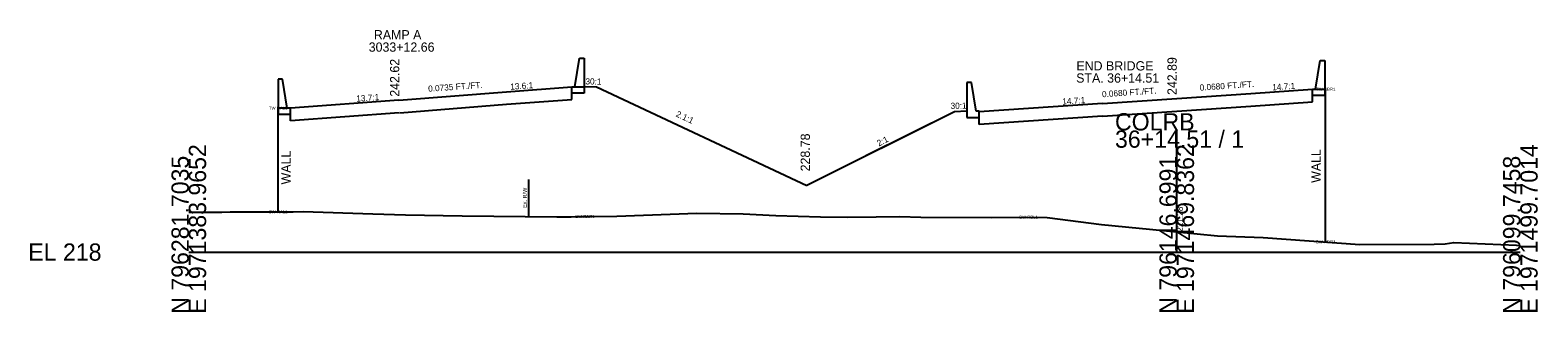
# Model space of a CAD drawing. Extents: x -26 to 1971766, y -10 to 796432.
# Drawn here: x -25.7 to 218.5, y 495.3 to 541 of the extents above; entities that cross this region are included whole.
import ezdxf

# ---------------------------------------------------------------- set-up
doc = ezdxf.new("R2010")
doc.units = 0
for name, color, linetype in [('BR_AUTO DIMENSION', 7, 'Continuous'), ('BR_BORDER LINES', 7, 'Continuous'), ('BR_CONCRETE', 7, 'Continuous'), ('BR_STRUCTURAL STEEL', 7, 'Continuous'), ('BR_TABLE LINES', 7, 'Continuous'), ('Default', 7, 'Continuous'), ('North Arrow', 7, 'Continuous'), ('RD_DDB_Profile_Lbl', 7, 'Continuous'), ('RD_EX_Road', 7, 'Continuous'), ('RD_HC_CL_Rel', 7, 'Continuous'), ('RD_PD_ALT1_TrvlWay', 7, 'Continuous'), ('RD_PD_ALT2_TnTmp', 7, 'Continuous'), ('RD_PD_Final_LnLine', 7, 'Continuous'), ('RD_PD_GR', 7, 'Continuous'), ('RD_PD_MedBWall', 7, 'Continuous'), ('RD_PD_WallFill', 7, 'Continuous'), ('RD_SHT_IplotShp', 7, 'Continuous')]:
    doc.layers.add(name, color=color, linetype=linetype)

msp = doc.modelspace()

# ---------------------------------------------------------------- linework, layer by layer
at = {"layer": 'BR_AUTO DIMENSION'}
for p, q in [((160, 505), (160, 524.71)), ((0, 505), (160, 505)), ((160, 505), (215.65, 505))]:
    msp.add_line(p, q, dxfattribs=at)
at = {"layer": 'BR_BORDER LINES'}
msp.add_lwpolyline([(0, 511.49), (0.86, 511.47), (5.34, 511.48), (6.72, 511.51), (14.85, 511.52), (16.9, 511.54), (18.51, 511.57), (29.83, 511.18), (35.07, 511.02), (44.25, 510.89), (59.59, 510.69), (61.94, 510.72), (63.56, 510.75), (65.04, 510.79), (69.35, 510.83), (82.27, 511.3), (89.76, 511.2), (95.06, 510.95), (102.3, 510.72), (106.69, 510.63), (111.33, 510.69), (115.15, 510.75), (118.55, 510.65), (130.01, 510.58), (135.73, 510.65), (139, 510.62), (147.82, 509.49), (160, 508.28), (166.59, 507.62), (174, 507.37), (189.66, 506.24), (201.72, 506.3), (203.46, 506.35), (204.9, 506.56), (215.05, 506.1), (215.65, 506.09)], dxfattribs=at)
at = {"layer": 'BR_STRUCTURAL STEEL'}
for p, q in [((62.01, 531.77), (64.06, 531.77)), ((182, 531.39), (184.05, 531.39)), ((184.05, 531.39), (184.05, 506.64)), ((16.45, 528.33), (14.4, 528.33)), ((14.4, 528.33), (14.4, 511.52))]:
    msp.add_line(p, q, dxfattribs=at)
at = {"layer": 'BR_TABLE LINES'}
msp.add_line((55, 516.76), (55, 510.76), dxfattribs=at)
at = {"layer": 'North Arrow'}
for p, q in [((34.04, 529.61), (51.43, 530.99)), ((148, 529.08), (160, 529.9)), ((160, 529.9), (172, 530.71))]:
    msp.add_line(p, q, dxfattribs=at)
at = {"layer": 'RD_EX_Road'}
for p, q in [((62.01, 529.73), (62.01, 531.77)), ((182, 529.35), (182, 531.39)), ((16.45, 526.29), (16.45, 528.33)), ((34.09, 527.58), (16.45, 526.29)), ((34.2, 527.59), (51.43, 528.95)), ((51.43, 528.95), (62.01, 529.73)), ((128, 525.68), (128, 527.72)), ((148, 527.04), (160, 527.86)), ((160, 527.86), (172, 528.67)), ((172, 528.67), (182, 529.35)), ((148, 527.04), (128, 525.68))]:
    msp.add_line(p, q, dxfattribs=at)
at = {"layer": 'RD_PD_Final_LnLine'}
for p, q in [((64.01, 531.84), (66.01, 531.77)), ((66.01, 531.77), (100.07, 515.78)), ((124, 527.75), (100.07, 515.78)), ((124, 527.75), (109.64, 520.57)), ((126, 527.81), (124, 527.75))]:
    msp.add_line(p, q, dxfattribs=at)
at = {"layer": 'RD_PD_GR'}
for p, q in [((62.51, 531.77), (63.26, 536.44)), ((63.26, 536.44), (64.01, 536.44)), ((64.01, 536.44), (64.01, 530.77)), ((182.5, 531.39), (183.25, 536.06)), ((183.25, 536.06), (184, 536.06)), ((184, 536.06), (184, 530.39)), ((15.2, 533), (14.45, 533)), ((14.45, 533), (14.45, 527.33)), ((15.95, 528.33), (15.2, 533)), ((126.75, 532.48), (126, 532.48)), ((126, 532.48), (126, 526.81)), ((127.5, 527.81), (126.75, 532.48)), ((62.01, 530.77), (62.01, 531.77)), ((62.01, 531.77), (62.51, 531.77)), ((64.01, 530.77), (62.01, 530.77)), ((182, 530.39), (182, 531.39)), ((182, 531.39), (182.5, 531.39)), ((184, 530.39), (182, 530.39)), ((16.45, 528.33), (15.95, 528.33)), ((16.45, 527.33), (16.45, 528.33)), ((128, 527.81), (127.5, 527.81)), ((128, 526.81), (128, 527.81)), ((14.45, 527.33), (16.45, 527.33)), ((126, 526.81), (128, 526.81))]:
    msp.add_line(p, q, dxfattribs=at)
at = {"layer": 'RD_PD_MedBWall'}
for p, q in [((51.43, 530.99), (62.01, 531.77)), ((172, 530.71), (182, 531.39)), ((34.04, 529.61), (16.45, 528.33)), ((148, 529.08), (128, 527.72))]:
    msp.add_line(p, q, dxfattribs=at)

# ---------------------------------------------------------------- texts
at = {"layer": 'BR_AUTO DIMENSION'}
for s, p in [('COLRB', (150, 524.71)), ('36+14.51 / 1', (150, 521.91)), ('EL 218', (-26, 503.6))]:
    msp.add_text(s, height=2.8, dxfattribs=at).set_placement(p)
for s, p in [('N 796281.7035', (0, 495)), ('E 1971383.9652', (2.8, 495)), ('N 796146.6991', (160, 495)), ('E 1971469.8362', (162.8, 495)), ('N 796099.7458', (215.65, 495)), ('E 1971499.7014', (218.45, 495))]:
    msp.add_text(s, height=2.8, rotation=90, dxfattribs=at).set_placement(p)
at = {"layer": 'BR_CONCRETE'}
for s, rotation, p in [('0.0735 FT./FT.', 4.2019, (38.8, 530.97)), ('13.6:1', 4.2019, (52.1, 531.29)), ('30:1', 359.1385, (64.23, 532.17)), ('0.0680 FT./FT.', 3.8901, (163.75, 531.15)), ('0.0680 FT./FT.', 3.8901, (147.93, 530.08)), ('2.1:1', 334.8507, (78.79, 527.02)), ('30:1', 0.8615, (123.38, 528.2)), ('2:1', 27.5168, (111.76, 522.1))]:
    msp.add_text(s, height=1, rotation=rotation, dxfattribs=at).set_placement(p)
at = {"layer": 'BR_TABLE LINES'}
msp.add_text('Ex. R/W ', height=0.65, rotation=90, dxfattribs=at).set_placement((54.75, 512.15))
at = {"layer": 'Default'}
msp.add_text('228.78', height=1.5, rotation=90, dxfattribs=at).set_placement((100.59, 518.08))
at = {"layer": 'RD_DDB_Profile_Lbl'}
for s, p in [('TW RBR1', (182.59, 531.14)), ('TW RAL1', (12.98, 528.08)), ('BW RAL1', (12.96, 511.27)), ('BW RAR1', (62.58, 510.51)), ('BW RBL1', (134.5, 510.4)), ('BW RBR1', (182.56, 506.39))]:
    msp.add_text(s, height=0.5, dxfattribs=at).set_placement(p)
at = {"layer": 'RD_HC_CL_Rel'}
for s, p in [(' 242.62', (34.09, 529.62)), (' 242.89', (160, 529.9))]:
    msp.add_text(s, height=1.5, rotation=90, dxfattribs=at).set_placement(p)
at = {"layer": 'RD_PD_ALT1_TrvlWay'}
for s, rotation, p in [('14.7:1', 3.8901, (175.5, 531.2)), ('13.7:1', 4.1657, (27.16, 529.36)), ('14.7:1', 3.8901, (141.5, 528.89))]:
    msp.add_text(s, height=1, rotation=rotation, dxfattribs=at).set_placement(p)
at = {"layer": 'RD_PD_ALT2_TnTmp'}
for s, p in [('END BRIDGE', (143.75, 534.43)), ('STA. 36+14.51', (143.72, 532.46))]:
    msp.add_text(s, height=1.5, dxfattribs=at).set_placement(p)
for p in [(16.5, 515.96), (183.32, 516.22)]:
    msp.add_text('WALL', height=1.5, rotation=90, dxfattribs=at).set_placement(p)
at = {"layer": 'RD_PD_WallFill'}
for s, p in [('RAMP A', (29.98, 539.47)), ('3033+12.66', (29.14, 537.47))]:
    msp.add_text(s, height=1.5, dxfattribs=at).set_placement(p)
at = {"layer": 'RD_SHT_IplotShp'}
msp.add_text('221.28', height=1, rotation=90, dxfattribs=at).set_placement((161, 508.28))

doc.saveas('drawing.dxf')
